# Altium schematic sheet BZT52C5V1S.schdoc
size 127 x 101 mm
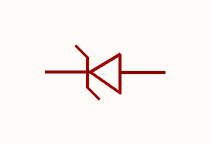
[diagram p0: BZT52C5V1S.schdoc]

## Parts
ZD?  bzt52c5v1s w8  [SOD-323_L1.8-W1.3-LS2.5-RD]  (value not drawn)

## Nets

Not connected (* = marked no-connect by the designer): ZD? 1(K) 2(A)

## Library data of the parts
ZD? = bzt52c5v1s w8: 二极管配置:1个独立式;稳压值(标称值):5.1V;稳压值(范围):4.8V~5.4V;耗散功率(Pd):200mW;; Manufacturer: CJ(江苏长电/长晶); AddInBom: yes; ModelId: db63db13d9e342eb939127d413d6200b; ModelTransform: 104.3305,51.181,0,0,0,0,0,-0.004,0; Diode Configuration: 1个独立式; Zener Voltage(Nom): 5.1V; Reverse Leakage Current (Ir): 2uA@2V; Pd - Power Dissipation: 200mW; Impedance(Zzt): 60Ω; Impedance(Zzk): 480Ω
